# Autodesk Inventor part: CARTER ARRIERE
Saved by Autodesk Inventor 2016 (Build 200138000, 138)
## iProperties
Created: 2013-10
Part Number: CARTER ARRIERE
Material: Générique
Document SubType Name: Modeling
Designer: Bruno
Density: 1 g/cm^3
Appearance: Par défaut
Author: Bruno
Sending System: SolidWorks 2013
Last Author: christophe
Last Saved: 2014-02-15
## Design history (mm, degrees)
feature "Boss.-Extru.41"
node "Solide1"
